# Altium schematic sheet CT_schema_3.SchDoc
size 313 x 200 mm
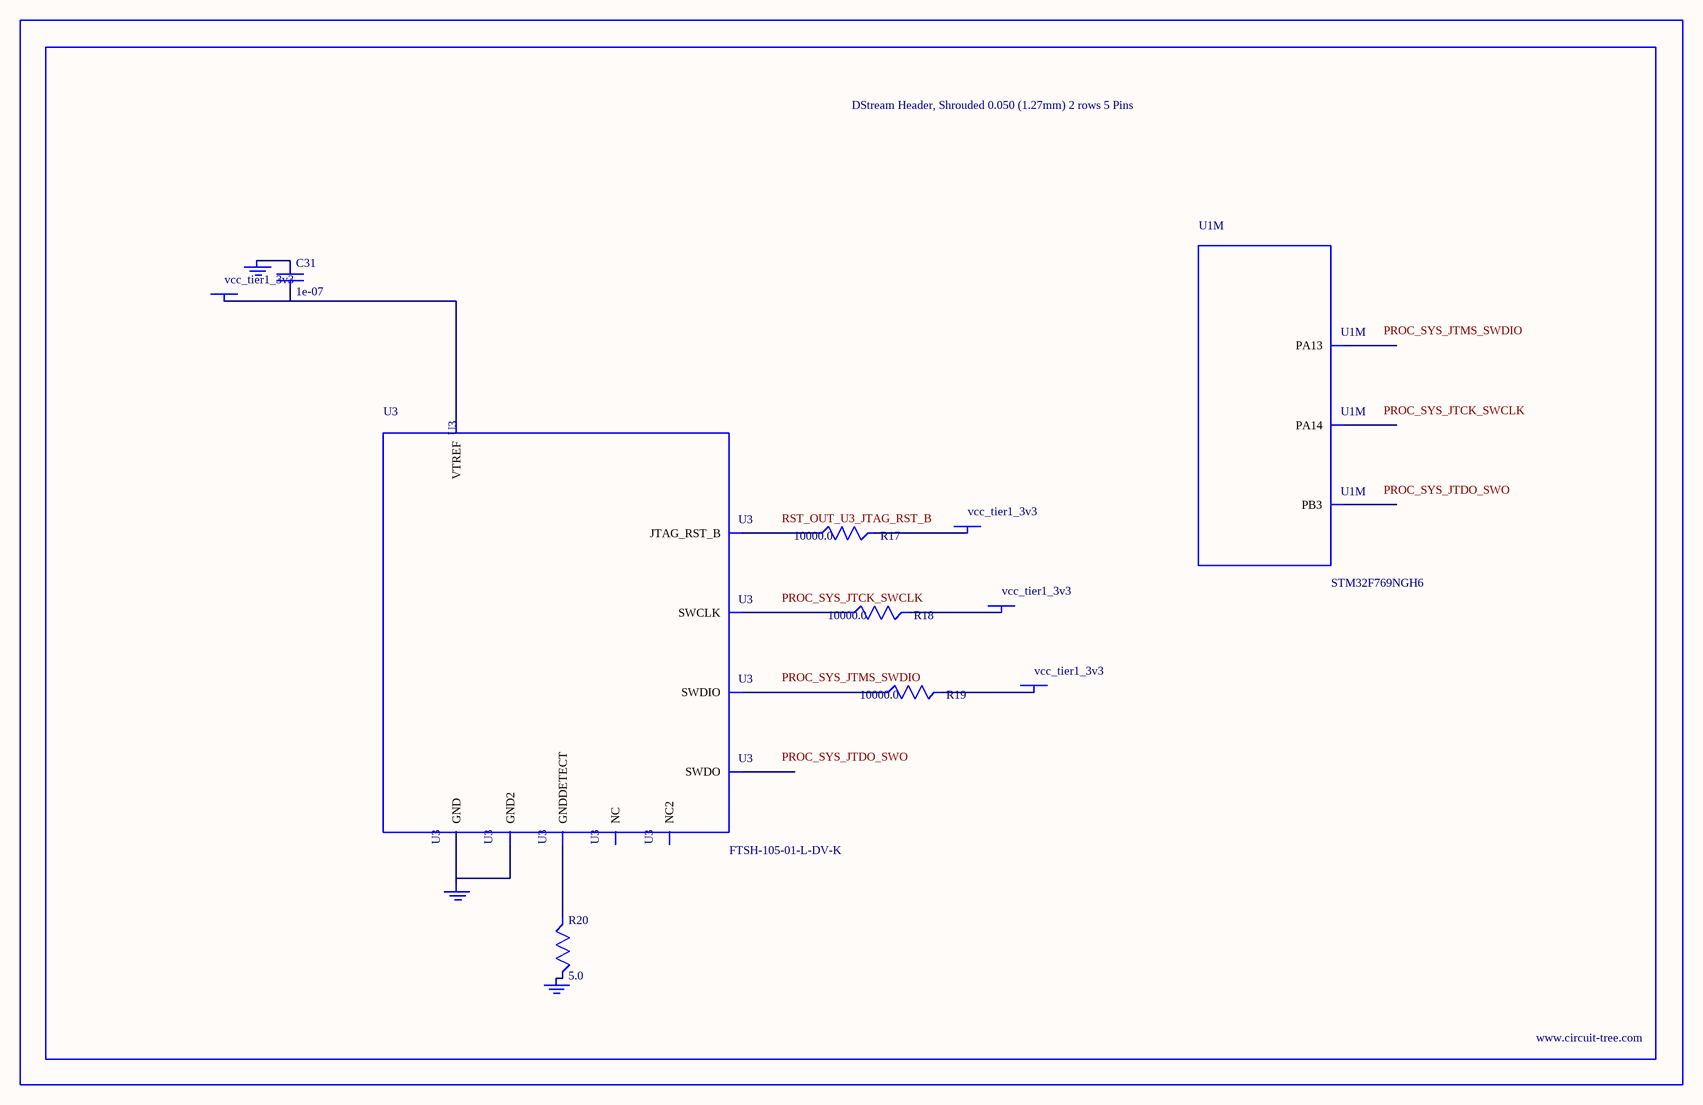
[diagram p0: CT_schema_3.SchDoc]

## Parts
BORDER2  (no value)
C31  1e-07  [C0402]
GND_INSTANCE_2_0  (no value)
GND_INSTANCE_2_1  (no value)
GND_INSTANCE_2_2  (no value)
POWER_INSTANCE_2_0  vcc_tier1_3v3
POWER_INSTANCE_2_1  vcc_tier1_3v3
POWER_INSTANCE_2_2  vcc_tier1_3v3
POWER_INSTANCE_2_3  vcc_tier1_3v3
R17  10000.0  [R0603]
R18  10000.0  [R0603]
R19  10000.0  [R0603]
R20  5.0  [R0603]
U1  STM32F769NGH6  [TFBGA216]  (part M of 17)
U3  FTSH-105-01-L-DV-K  [SAMTEC_FTSH-105-01-L-DV-K]

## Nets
NetC31_1: C31.1 GND_INSTANCE_2_0.0(GND)
NetC31_2: C31.2 POWER_INSTANCE_2_0.0(PWR) U3.1(VTREF)
NetGND_INSTANCE_2_1_0: GND_INSTANCE_2_1.0(GND) R20.2
NetGND_INSTANCE_2_2_0: GND_INSTANCE_2_2.0(GND) U3.3(GND) U3.5(GND2)
NetPOWER_INSTANCE_2_1_0: POWER_INSTANCE_2_1.0(PWR) R19.2
NetPOWER_INSTANCE_2_2_0: POWER_INSTANCE_2_2.0(PWR) R18.2
NetPOWER_INSTANCE_2_3_0: POWER_INSTANCE_2_3.0(PWR) R17.2
NetR17_1: R17.1 U3.10(JTAG_RST_B)
NetR18_1: R18.1 U3.4(SWCLK)
NetR19_1: R19.1 U3.2(SWDIO)
NetR20_1: R20.1 U3.9(GNDDETECT)

Not connected (* = marked no-connect by the designer): U1 A10(PB3) A14(PA14) A15(PA13); U3 6(SWDO) 7(NC) 8(NC2)

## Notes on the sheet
- Labels drawn without touching a wire or pin: PROC_SYS_JTCK_SWCLK, PROC_SYS_JTDO_SWO, PROC_SYS_JTMS_SWDIO, RST_OUT_U3_JTAG_RST_B

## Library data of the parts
BORDER2 = BORDER_PAGE2
C31 = C0402C104K3RACTU
GND_INSTANCE_2_0-GND_INSTANCE_2_2 = GND
POWER_INSTANCE_2_0-POWER_INSTANCE_2_3 = PWR
R17-R19 = RC0603JR-0710KL
R20 = ERJ-3GEYJ5R1V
